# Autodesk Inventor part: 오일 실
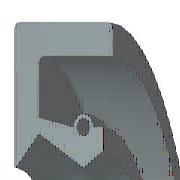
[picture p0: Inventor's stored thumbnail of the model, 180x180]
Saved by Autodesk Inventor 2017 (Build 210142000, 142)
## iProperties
IsCustomPart: 0
Created: 2014-10
Part Number: 오일 실
Material: 고무
Description: 오일-실
Document SubType Name: Modeling
Standard: KS B 2804
Designer: KYOUNG IL JANG
Standards Organization: KS
Language: ko-KR
Size Designation: D - 17 32 8
Categories: <MemberInstance><Categories><Category DisplayName="샤프트 부품" InternalName="7f7aeb1f-a693-4053-b835-cee3144e0d98" Mnemonic="SHFT"><Category DisplayName="실링" Intern
Density: 0.93 g/cm^3
Mass: 2.28027 g
Surface Area: 32.1224 cm^2
Volume: 2.45191 cm^3
Appearance: 고무 - 검은색 - 버전 1.1
Author: SeoGD™ [www.esajin.kr]
Revision Number: 1
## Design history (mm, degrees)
revolve "본체" stored, may be unused: angle "d17" = 90 deg
revolve "스프링1" stored, may be unused: angle "d18" = 90 deg
body "Solid1"
sketch "스케치1"
  geometry: L1 (0, 16)-(8, 16); L2 (8, 14.25)-(1.75, 14.25); L3 (1.75, 10.25)-(4.9, 8.5); L4 (4.9, 8.5)-(0, 8.5); L5 (0, 0)-(9.586, 0) reference; L6 (4.9, 8.5)-(6.3, 9.375); L7 (0, 18)-(0, -3) reference; L8 (-1.941, 0)-(11.507, 0) reference; L9 (4.2, 10.6)-(1.75, 11.21); L10 (1.75, 11.21)-(1.75, 14.25); L11 (0, 16)-(0, 8.588); L12 (4.9, 8.5)-(0, 8.5); L13 (1.75, 10.25)-(0.152, 8.528); L14 (8, 16)-(8, 14.25); L15 (5.6, 10.6)-(6.3, 10.6); L16 (6.3, 10.6)-(6.3, 9.375); C1 r 0.455 at (4.9, 10.6); A1 r 0.7 centre (4.9, 10.6) between (5.6, 10.6) and (4.2, 10.6); A2 r 0.088 centre (0.088, 8.588) between (0, 8.588) and (0.152, 8.528); 1 further point
  constraints: 28 end point, 5 horizontal alignment, 5 point on line, 4 point on circle, 4 vertical alignment, 3 centre point, 3 tangent, 2 collinear, 2 horizontal, 2 perpendicular, 1 coincident, 1 parallel
  dimensions: "d0" = 32 diameter of L1 L5 (= SD2); "d1" = 1.75 distance of L1.end L2.start (= SD); "d2" = 0.91 diameter of C1 (= SPDI); "d3" = 1.4 diameter of A1 (= SPDA); "d4" = 17 diameter of L3.end L5 (= NND); "d5" = 20.5 diameter of L3.start L5 (= TKDM); "d7" = 22.42 diameter of L9.end L5 (= TKDM + 0.24 x SWDT); "d8" = 1.75 distance between parallel lines of L11 L10 (= SD); "d9" = 4.9 distance from line of L11 C1.centre (= SPDST); "d10" = 21.2 diameter of C1.centre L5 (= HLDM); "d11" = 0.0875 radius of A2 (= 0.25 x LAB); "d12" = 6.3 distance between parallel lines of L11 L16 (= SDI); "d13" = 18.75 diameter of L6.end L5 (= ABDM); "d14" = 8 distance from line of L11 L1.end (= SWDT)
fillet "모깎기1" dims "d6" = 0.3 (= RR)
other parameters: "SD2" = 32 [user parameter; used in 1 equation term], "SWDT" = 8 [user parameter; used in 2 equation terms], "RR" = 0.3 [user parameter; used in 1 equation term], "SD" = 1.75 [user parameter; used in 2 equation terms], "NND" = 17 [user parameter; used in 1 equation term], "SPDA" = 1.4 [user parameter; used in 1 equation term], "SPDI" = 0.91 [user parameter; used in 1 equation term], "TKDM" = 20.5 [user parameter; used in 2 equation terms], "HLDM" = 21.2 [user parameter; used in 1 equation term], "ABDM" = 18.75 [user parameter; used in 1 equation term], "SDI" = 6.3 [user parameter; used in 1 equation term], "SPDST" = 4.9 [user parameter; used in 1 equation term], "LAB" = 0.35 [user parameter; used in 1 equation term], "d15" = 0, "d16" = 0, "d19" = 0
